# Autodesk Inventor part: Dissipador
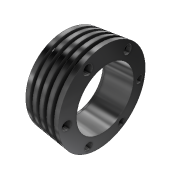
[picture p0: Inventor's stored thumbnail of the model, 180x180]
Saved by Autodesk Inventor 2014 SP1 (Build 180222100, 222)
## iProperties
Created: 2013-12
Part Number: Dissipador
Material: Generic
Document SubType Name: Modeling
Designer: User
Density: 1 g/cm^3
Appearance: Chrome - Polished Black
Author: User
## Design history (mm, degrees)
sketch "Sketch1" dims "d10" = 10
  geometry: L1 (0, 0)-(13.012, 0); L2 (0, 0)-(0, 13.5); L3 (10.5, 13.5)-(10.5, 0); L4 (1.275, 13.5)-(1.275, 10.5); L5 (1.275, 10.5)-(2.275, 10.5); L6 (2.275, 10.5)-(2.275, 13.5); L7 (3.55, 13.5)-(3.55, 10.5); L8 (3.55, 10.5)-(4.55, 10.5); L9 (4.55, 10.5)-(4.55, 13.5); L10 (5.825, 13.5)-(5.825, 10.5); L11 (5.825, 10.5)-(6.825, 10.5); L12 (6.825, 10.5)-(6.825, 13.5); L13 (8.1, 13.5)-(8.1, 10.5); L14 (8.1, 10.5)-(9.1, 10.5); L15 (9.1, 10.5)-(9.1, 13.5); L16 (0, 13.5)-(1.275, 13.5); L17 (2.275, 13.5)-(3.55, 13.5); L18 (4.55, 13.5)-(5.825, 13.5); L19 (6.825, 13.5)-(8.1, 13.5); L20 (9.1, 13.5)-(10.5, 13.5)
  constraints: 40 end point, 12 perpendicular, 2 horizontal, 2 parallel, 1 point on line, 21 other
  dimensions: "d0" = 10.5 distance of L2.end L3.start; "d2" = 1.275 distance between parallel lines of L4 L2; "d3" = 1 distance between parallel lines of L6 L4; "d4" = 21 diameter of L5 L1; "d7" = 2.275 distance of L4.start L7.start (= d2 + d3)
revolve "Revolution1" sketch "Sketch1" stored, may be unused: angle "d12" = 90 deg
sketch "Sketch2"
  geometry: C1 r 13.5 at (0, 0) reference; C2 r 9 at (0, 0)
  constraints: 1 centre point, 1 coincident
  dimensions: "d13" = 18 diameter of C2
extrude "Extrusion1" cut sketch "Sketch2" stored distance "d14" = 10; taper "d15" = 0 deg
sketch "Sketch3"
  geometry: C1 r 9 at (0, 0) reference; C2 r 13.5 at (0, 0) reference; C3 r 10 at (0, 0)
  constraints: 1 centre point, 1 coincident
  dimensions: "d16" = 20 diameter of C3
extrude "Extrusion2" cut sketch "Sketch3" distance "d17" = 1.5; taper "d18" = 0 deg
sketch "Sketch4" dims "d19" = 23
  geometry: C1 r 13.5 at (0, 0) reference; 2 further points
  constraints: 1 coincident, 1 vertical alignment, 2 other
hole "Hole1" sketch "Sketch4" at (0, 11.5) diameter "d20" = 2.5; stored, may be unused: countersink angle "d24" = 90 deg, drill point angle "d26" = 118 deg; dims "d21" = 6, "d22" = 4, "d23" = 2, "d25" = 8
pattern_circular "Circular Pattern1" dims angle "d28" = 360 deg
body "Solid1"
other parameters: "d1" = 27
